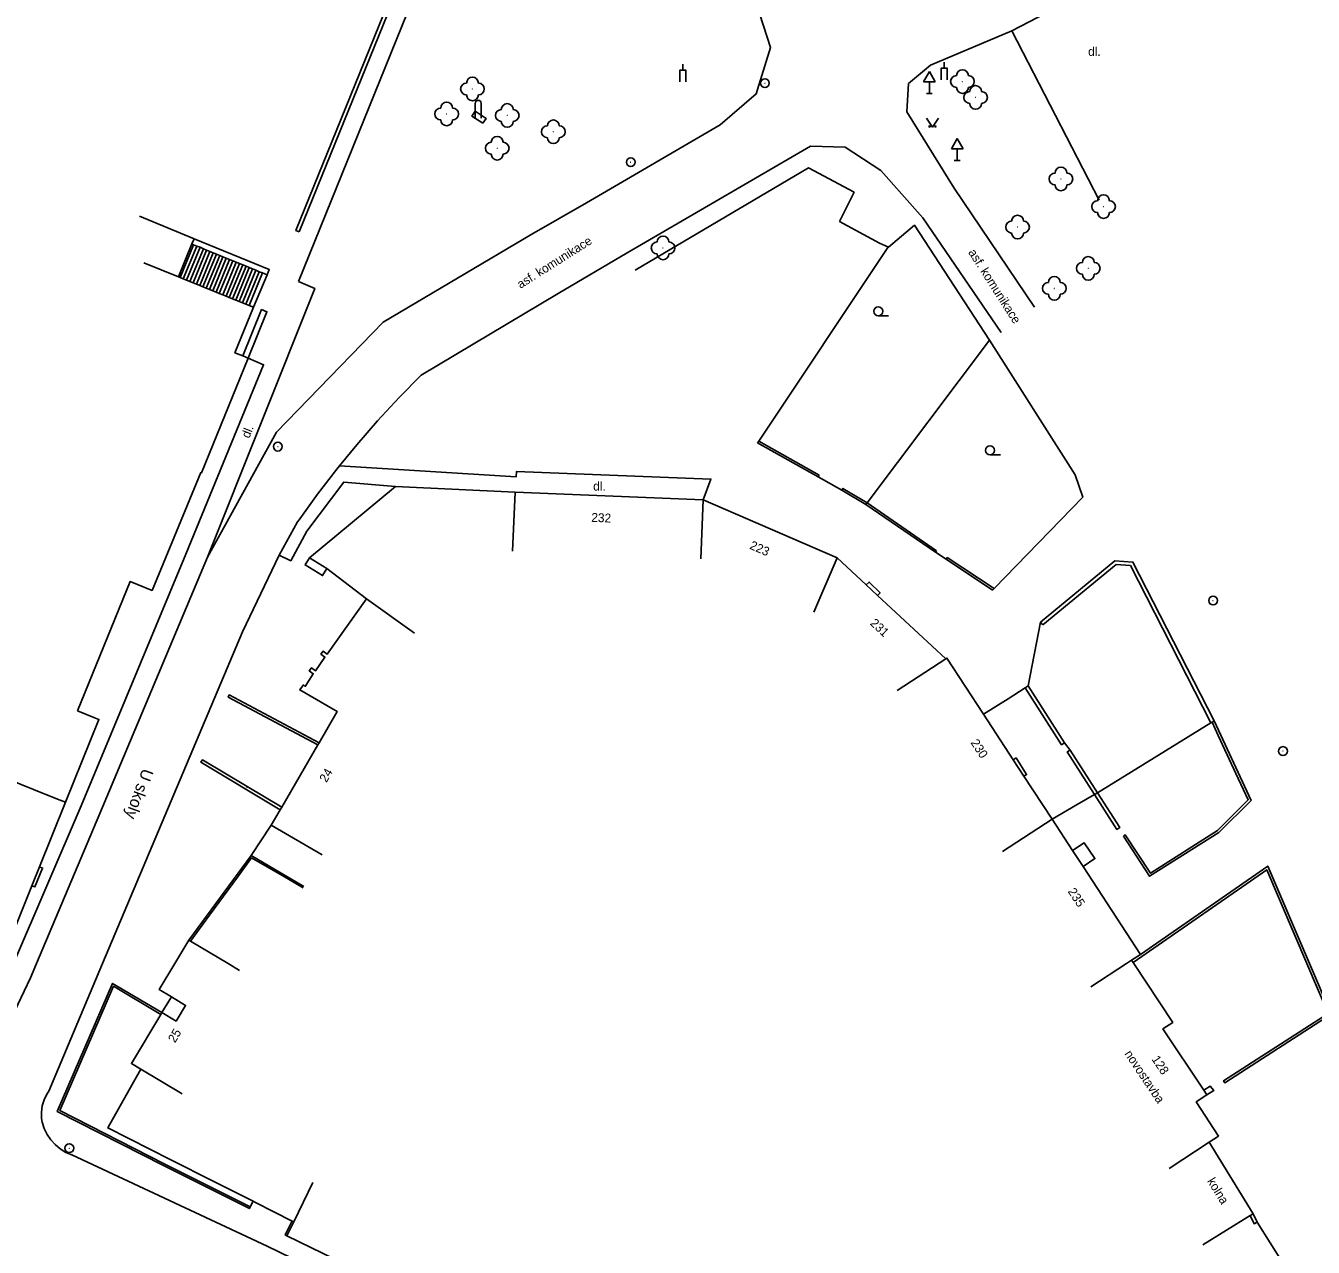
# Model space of a CAD drawing. Extents: x -582162 to -561283, y -1187583 to -1183539.
# Drawn here: x -578373.5 to -578264.6, y -1186024 to -1185920.7 of the extents above; entities that cross this region are included whole.
import ezdxf

# ---------------------------------------------------------------- set-up
doc = ezdxf.new("R2010")
doc.units = 0
for name, color, linetype in [('Vrstva 1', 7, 'Continuous'), ('Vrstva 10', 7, 'Continuous'), ('Vrstva 11', 7, 'Continuous'), ('Vrstva 13', 7, 'Continuous'), ('Vrstva 14', 7, 'Continuous'), ('Vrstva 3', 7, 'Continuous'), ('Vrstva 4', 7, 'Continuous'), ('Vrstva 6', 7, 'Continuous'), ('Vrstva 9', 7, 'Continuous')]:
    doc.layers.add(name, color=color, linetype=linetype)

# ---------------------------------------------------------------- blocks, each defined once
blk = doc.blocks.new('1.079')
at = {"layer": 'Vrstva 1'}
for radius in [0.75, 0.001]:
    blk.add_circle((0, -0.001), radius, dxfattribs=at)
blk = doc.blocks.new('3.130')
at = {"layer": 'Vrstva 1'}
blk.add_circle((0, 0), 0.001, dxfattribs=at)
for centre, start, end in [((-1, 0), 90, 270), ((0, 1), 0, 180), ((1, 0), 270, 90), ((0, -1), 180, 360)]:
    blk.add_arc(centre, 1, start, end, dxfattribs=at)
blk = doc.blocks.new('3.040')
at = {"layer": 'Vrstva 1'}
blk.add_line((0, -0.75), (1.75, -0.75), dxfattribs=at)
blk.add_circle((0, 0), 0.75, dxfattribs=at)
blk = doc.blocks.new('3.140')
at = {"layer": 'Vrstva 1'}
blk.add_lwpolyline([(-1, 1.5), (0, 0), (1, 1.5)], dxfattribs=at)
for centre in [(-0.5, 0.1), (0.5, 0.1)]:
    blk.add_circle(centre, 0.1, dxfattribs=at)
blk = doc.blocks.new('4.120')
at = {"layer": 'Vrstva 1'}
blk.add_line((0, 2), (0, 3), dxfattribs=at)
blk.add_lwpolyline([(-0.5, 0), (-0.5, 2), (0.5, 2), (0.5, 0)], dxfattribs=at)
blk = doc.blocks.new('4.140')
at = {"layer": 'Vrstva 1'}
for p, q in [((-0.5, 0), (-0.5, 2.5)), ((0.5, 0), (0.5, 2.5))]:
    blk.add_line(p, q, dxfattribs=at)
blk.add_arc((0, 2.5), 0.5, 0, 180, dxfattribs=at)
blk = doc.blocks.new('5.270')
at = {"layer": 'Vrstva 1'}
for p, q in [((0, 3.732), (-1, 2)), ((0, 3.732), (1, 2)), ((-1, 2), (1, 2)), ((-0.5, 0), (0.5, 0)), ((0, 0), (0, 2))]:
    blk.add_line(p, q, dxfattribs=at)

msp = doc.modelspace()

# ---------------------------------------------------------------- linework, layer by layer
at = {"layer": 'Vrstva 10'}
for points in [[(-578326.04, -1185935.66), (-578314.74, -1185929.06), (-578311.68, -1185926.46), (-578310.47, -1185922.53), (-578312.01, -1185917.81), (-578316.2, -1185914.48), (-578322.8, -1185910.47), (-578334.12, -1185904.09)], [(-578335.19, -1185904.77), (-578350.39, -1185942.33)], [(-578290.07, -1185921.12), (-578284.27, -1185918.07)], [(-578290.07, -1185921.12), (-578296.93, -1185924.04), (-578298.81, -1185925.58), (-578298.94, -1185927.96), (-578294.95, -1185934.42), (-578288.14, -1185944.49)], [(-578290.07, -1185921.12), (-578282.68, -1185935.44)], [(-578334.8, -1185928.94), (-578335.72, -1185928.33), (-578335.44, -1185927.92), (-578334.53, -1185928.53), (-578334.8, -1185928.94)], [(-578290.96, -1185946.64), (-578297.58, -1185936.93), (-578301.15, -1185932.93), (-578304.17, -1185930.95), (-578307.1, -1185930.89), (-578322.61, -1185939.9)], [(-578343.24, -1185945.76), (-578330.66, -1185938.33), (-578326.04, -1185935.66)], [(-578353.05, -1185941.76), (-578352.86, -1185941.32), (-578359.23, -1185938.7)], [(-578360.41, -1185941.98), (-578359.27, -1185939.21)], [(-578360.14, -1185942.09), (-578358.99, -1185939.32)], [(-578359.86, -1185942.2), (-578358.72, -1185939.43)], [(-578359.58, -1185942.31), (-578358.44, -1185939.55)], [(-578359.27, -1185939.21), (-578359.41, -1185939.15)], [(-578359.3, -1185942.43), (-578358.16, -1185939.66)], [(-578358.99, -1185939.32), (-578359.27, -1185939.21)], [(-578359.02, -1185942.54), (-578357.88, -1185939.78)], [(-578358.72, -1185939.43), (-578358.99, -1185939.32)], [(-578358.75, -1185942.65), (-578357.61, -1185939.89)], [(-578358.44, -1185939.55), (-578358.72, -1185939.43)], [(-578358.47, -1185942.77), (-578357.33, -1185940)], [(-578358.16, -1185939.66), (-578358.44, -1185939.55)], [(-578358.2, -1185942.88), (-578357.05, -1185940.12)], [(-578357.88, -1185939.78), (-578358.16, -1185939.66)], [(-578357.61, -1185939.89), (-578357.88, -1185939.78)], [(-578357.33, -1185940), (-578357.61, -1185939.89)], [(-578357.05, -1185940.12), (-578357.33, -1185940)], [(-578356.78, -1185940.23), (-578357.05, -1185940.12)], [(-578322.61, -1185939.9), (-578328.44, -1185943.34), (-578340.01, -1185950.23)], [(-578357.91, -1185943), (-578356.78, -1185940.23)], [(-578357.63, -1185943.11), (-578356.5, -1185940.34)], [(-578357.35, -1185943.22), (-578356.22, -1185940.46)], [(-578357.09, -1185943.33), (-578355.94, -1185940.58)], [(-578356.8, -1185943.45), (-578355.67, -1185940.69)], [(-578356.5, -1185940.34), (-578356.78, -1185940.23)], [(-578356.52, -1185943.56), (-578355.39, -1185940.8)], [(-578356.22, -1185940.46), (-578356.5, -1185940.34)], [(-578356.25, -1185943.67), (-578355.11, -1185940.92)], [(-578355.94, -1185940.58), (-578356.22, -1185940.46)], [(-578355.98, -1185943.78), (-578354.83, -1185941.03)], [(-578355.67, -1185940.69), (-578355.94, -1185940.58)], [(-578355.69, -1185943.9), (-578354.56, -1185941.14)], [(-578355.39, -1185940.8), (-578355.67, -1185940.69)], [(-578355.41, -1185944.01), (-578354.28, -1185941.26)], [(-578355.11, -1185940.92), (-578355.39, -1185940.8)], [(-578354.83, -1185941.03), (-578355.11, -1185940.92)], [(-578354.56, -1185941.14), (-578354.83, -1185941.03)], [(-578354.28, -1185941.26), (-578354.56, -1185941.14)], [(-578354, -1185941.37), (-578354.28, -1185941.26)], [(-578350.39, -1185942.33), (-578349.02, -1185942.9), (-578358.08, -1185965.64)], [(-578355.13, -1185944.12), (-578354, -1185941.37)], [(-578354.85, -1185944.23), (-578353.72, -1185941.49)], [(-578354.57, -1185944.34), (-578353.45, -1185941.6)], [(-578354.21, -1185944.49), (-578353.05, -1185941.76)], [(-578353.72, -1185941.49), (-578354, -1185941.37)], [(-578353.45, -1185941.6), (-578353.72, -1185941.49)], [(-578353.05, -1185941.76), (-578353.45, -1185941.6)], [(-578354.66, -1185948.79), (-578353.06, -1185944.88), (-578353.51, -1185944.7), (-578355.1, -1185948.61)], [(-578358.08, -1185965.64), (-578352.25, -1185955.07), (-578343.24, -1185945.76)], [(-578374.5, -1186000), (-578368.76, -1185986.67), (-578359.91, -1185965.38), (-578353.34, -1185949.36), (-578354.66, -1185948.79)], [(-578340.01, -1185950.23), (-578341.88, -1185952.14), (-578343.7, -1185954.1), (-578345.45, -1185956.12), (-578346.92, -1185957.91)], [(-578346.92, -1185957.91), (-578347.15, -1185958.19), (-578348.78, -1185960.31), (-578350.35, -1185962.48), (-578350.47, -1185962.65), (-578352.02, -1185965.46)], [(-578316.17, -1185960.77), (-578315.52, -1185959.03), (-578331.96, -1185958.39), (-578331.99, -1185958.84), (-578346.92, -1185957.91)], [(-578342.2, -1185959.66), (-578346.57, -1185959.28), (-578349.69, -1185963.42), (-578351.05, -1185965.94), (-578352.02, -1185965.46)], [(-578304.43, -1185959.96), (-578306.43, -1185958.83)], [(-578295.62, -1185965.81), (-578296.53, -1185965.22)], [(-578358.08, -1185965.64), (-578367.19, -1185987.3), (-578372.56, -1186000)], [(-578352.02, -1185965.46), (-578355.12, -1185971.94), (-578366.96, -1186000)], [(-578347.99, -1185966.59), (-578348.35, -1185967.19), (-578349.84, -1185966.29), (-578349.47, -1185965.69)], [(-578349.47, -1185965.69), (-578347.99, -1185966.59)], [(-578301.42, -1185968.86), (-578301.21, -1185968.64), (-578302.12, -1185967.74), (-578302.37, -1185967.98)], [(-578285.13, -1185981.94), (-578285.61, -1185981.32)], [(-578289.95, -1185982.76), (-578289.71, -1185982.61), (-578288.82, -1185984.01), (-578289.04, -1185984.15)], [(-578354.73, -1185985.03), (-578354.78, -1185985.1)], [(-578354.4, -1185990.87), (-578352.7, -1185988.3)], [(-578284.92, -1185990.45), (-578283.94, -1185989.79), (-578283.04, -1185991.12), (-578284.04, -1185991.79)], [(-578372.94, -1185993.42), (-578372.68, -1185993.52), (-578372.04, -1185991.92), (-578372.3, -1185991.82)], [(-578372.56, -1186000), (-578373.06, -1186001.19), (-578375.19, -1186005.72), (-578377.88, -1186010), (-578378.19, -1186010.37), (-578378.55, -1186010.68), (-578378.95, -1186010.91), (-578379.39, -1186011.08), (-578379.85, -1186011.16), (-578380.31, -1186011.17), (-578380.78, -1186011.1), (-578381.22, -1186010.95), (-578381.63, -1186010.73), (-578405.48, -1186000)], [(-578366.96, -1186000), (-578371.51, -1186010.78), (-578371.68, -1186011.05), (-578371.9, -1186011.53), (-578372.06, -1186012.04), (-578372.13, -1186012.57), (-578372.12, -1186013.1), (-578372.06, -1186013.41), (-578371.89, -1186013.94), (-578371.65, -1186014.44), (-578371.34, -1186014.9), (-578370.97, -1186015.31), (-578370.54, -1186015.67), (-578370.06, -1186015.96), (-578369.55, -1186016.18), (-578353.03, -1186023.9), (-578334.84, -1186032.75), (-578321.02, -1186039.95), (-578303.35, -1186050.31), (-578281.8, -1186064.68)], [(-578361.94, -1186004.14), (-578360.74, -1186004.86), (-578359.94, -1186003.53), (-578361.14, -1186002.81)], [(-578273.56, -1186011.09), (-578272.98, -1186010.73), (-578273.28, -1186010.37), (-578273.82, -1186010.7)], [(-578354.24, -1186020.1), (-578354.47, -1186020.57)], [(-578350.94, -1186021.77), (-578351.51, -1186022.94), (-578351.37, -1186023.01)], [(-578269.31, -1186021.87), (-578267.13, -1186025.35)]]:
    msp.add_lwpolyline(points, dxfattribs=at)
at = {"layer": 'Vrstva 4'}
for points in [[(-578359.23, -1185938.7), (-578363.85, -1185936.8)], [(-578359.41, -1185939.15), (-578359.23, -1185938.7)], [(-578360.55, -1185941.92), (-578359.41, -1185939.15)], [(-578360.55, -1185941.92), (-578363.47, -1185940.73)], [(-578360.41, -1185941.98), (-578360.55, -1185941.92)], [(-578360.14, -1185942.09), (-578360.41, -1185941.98)], [(-578359.86, -1185942.2), (-578360.14, -1185942.09)], [(-578359.58, -1185942.31), (-578359.86, -1185942.2)], [(-578359.3, -1185942.43), (-578359.58, -1185942.31)], [(-578359.02, -1185942.54), (-578359.3, -1185942.43)], [(-578358.75, -1185942.65), (-578359.02, -1185942.54)], [(-578358.47, -1185942.77), (-578358.75, -1185942.65)], [(-578358.2, -1185942.88), (-578358.47, -1185942.77)], [(-578357.91, -1185943), (-578358.2, -1185942.88)], [(-578357.63, -1185943.11), (-578357.91, -1185943)], [(-578357.35, -1185943.22), (-578357.63, -1185943.11)], [(-578357.09, -1185943.33), (-578357.35, -1185943.22)], [(-578356.8, -1185943.45), (-578357.09, -1185943.33)], [(-578356.52, -1185943.56), (-578356.8, -1185943.45)], [(-578356.25, -1185943.67), (-578356.52, -1185943.56)], [(-578355.98, -1185943.78), (-578356.25, -1185943.67)], [(-578355.69, -1185943.9), (-578355.98, -1185943.78)], [(-578355.1, -1185948.61), (-578355.77, -1185948.34), (-578354.21, -1185944.49)], [(-578355.41, -1185944.01), (-578355.69, -1185943.9)], [(-578355.13, -1185944.12), (-578355.41, -1185944.01)], [(-578354.85, -1185944.23), (-578355.13, -1185944.12)], [(-578354.57, -1185944.34), (-578354.85, -1185944.23)], [(-578354.21, -1185944.49), (-578354.57, -1185944.34)], [(-578369.07, -1185978.62), (-578364.64, -1185967.69), (-578362.77, -1185968.45), (-578358.66, -1185958.48), (-578358.59, -1185958.5), (-578354.66, -1185948.79)], [(-578354.66, -1185948.79), (-578355.1, -1185948.61)], [(-578332.07, -1185960.13), (-578332.28, -1185965.12)], [(-578316.17, -1185960.77), (-578332.07, -1185960.13)], [(-578316.37, -1185965.77), (-578316.17, -1185960.77)], [(-578304.83, -1185965.7), (-578316.17, -1185960.77)], [(-578306.82, -1185970.28), (-578304.83, -1185965.7)], [(-578302.37, -1185967.98), (-578304.83, -1185965.7)], [(-578301.42, -1185968.86), (-578302.37, -1185967.98)], [(-578348.65, -1185981.34), (-578347.11, -1185978.69), (-578350.29, -1185976.85), (-578349.98, -1185976.44), (-578349.82, -1185976.56), (-578349.14, -1185975.49), (-578349.48, -1185975.24), (-578349.3, -1185975), (-578348.96, -1185975.25), (-578348.16, -1185974.08), (-578348.5, -1185973.83), (-578348.32, -1185973.59), (-578347.98, -1185973.84), (-578344.63, -1185969.16)], [(-578344.63, -1185969.16), (-578340.57, -1185972.07)], [(-578295.64, -1185974.22), (-578301.42, -1185968.86)], [(-578299.75, -1185976.9), (-578295.64, -1185974.22)], [(-578295.64, -1185974.22), (-578295.56, -1185974.17), (-578292.46, -1185978.92)], [(-578370.11, -1185986.36), (-578367.27, -1185979.35), (-578367.7, -1185979.18)], [(-578367.7, -1185979.18), (-578369.07, -1185978.62)], [(-578292.46, -1185978.92), (-578289.95, -1185982.76)], [(-578351.81, -1185986.77), (-578348.75, -1185981.51)], [(-578348.75, -1185981.51), (-578348.65, -1185981.34)], [(-578289.95, -1185982.76), (-578289.04, -1185984.15)], [(-578374.75, -1185984.5), (-578371.91, -1185985.64)], [(-578289.04, -1185984.15), (-578286.66, -1185987.79)], [(-578371.91, -1185985.64), (-578370.55, -1185986.18)], [(-578370.11, -1185986.36), (-578372.3, -1185991.82)], [(-578370.55, -1185986.18), (-578370.11, -1185986.36)], [(-578352.7, -1185988.3), (-578351.94, -1185986.99)], [(-578351.94, -1185986.99), (-578351.81, -1185986.77)], [(-578290.85, -1185990.52), (-578286.66, -1185987.79)], [(-578286.66, -1185987.79), (-578284.92, -1185990.45)], [(-578348.38, -1185990.81), (-578352.7, -1185988.3)], [(-578284.92, -1185990.45), (-578284.04, -1185991.79)], [(-578372.3, -1185991.82), (-578372.94, -1185993.42)], [(-578284.04, -1185991.79), (-578279.19, -1185999.23)], [(-578372.94, -1185993.42), (-578375.58, -1186000)], [(-578359.66, -1185998.01), (-578360.85, -1186000)], [(-578359.53, -1185998.09), (-578359.66, -1185998.01)], [(-578356.34, -1186000), (-578359.53, -1185998.09)], [(-578360.85, -1186000), (-578362.17, -1186002.2), (-578361.14, -1186002.81)], [(-578355.37, -1186000.58), (-578356.34, -1186000)], [(-578280.37, -1186000), (-578283.37, -1186001.96)], [(-578279.93, -1185999.71), (-578280.37, -1186000)], [(-578279.19, -1185999.23), (-578279.93, -1185999.71)], [(-578279.93, -1185999.71), (-578279.81, -1185999.9)], [(-578279.81, -1185999.9), (-578279.74, -1186000)], [(-578279.74, -1186000), (-578276.46, -1186004.97), (-578277.29, -1186005.52), (-578273.82, -1186010.7)], [(-578361.14, -1186002.81), (-578361.94, -1186004.14)], [(-578362.03, -1186004.29), (-578364.52, -1186008.45), (-578363.72, -1186008.93)], [(-578361.94, -1186004.14), (-578362.03, -1186004.29)], [(-578363.72, -1186008.93), (-578360.24, -1186011.02)], [(-578273.82, -1186010.7), (-578273.56, -1186011.09)], [(-578273.56, -1186011.09), (-578274.47, -1186011.7), (-578272.59, -1186014.58), (-578273.37, -1186015.09)], [(-578273.37, -1186015.09), (-578276.76, -1186017.32)], [(-578273.37, -1186015.09), (-578269.65, -1186021.15)], [(-578349.18, -1186018.51), (-578350.8, -1186021.84)], [(-578350.8, -1186021.84), (-578351.37, -1186023.01)], [(-578269.91, -1186021.31), (-578273.91, -1186023.77)], [(-578269.65, -1186021.15), (-578269.91, -1186021.31)], [(-578351.37, -1186023.01), (-578334.11, -1186031.42)]]:
    msp.add_lwpolyline(points, dxfattribs=at)
at = {"layer": 'Vrstva 9'}
for points in [[(-578347.57, -1185930.52), (-578338.04, -1185907), (-578358.01, -1185896.59)], [(-578350.33, -1185938.13), (-578347.3, -1185930.63), (-578337.66, -1185906.86)], [(-578347.57, -1185930.52), (-578350.61, -1185938.02), (-578350.33, -1185938.13)], [(-578304.64, -1185937.26), (-578303.4, -1185934.77), (-578307.26, -1185932.72), (-578321.93, -1185941.36)], [(-578301.26, -1185939.08), (-578304.64, -1185937.26)], [(-578291.95, -1185947.29), (-578298.3, -1185937.57), (-578300.5, -1185939.42), (-578301.26, -1185939.08)], [(-578300.55, -1185939.46), (-578311.47, -1185955.83)], [(-578291.95, -1185947.29), (-578302.31, -1185961.04)], [(-578291.55, -1185968.29), (-578284.07, -1185960.56), (-578284.7, -1185958.66), (-578291.95, -1185947.29)], [(-578311.47, -1185955.83), (-578311.56, -1185955.96)], [(-578306.43, -1185958.83), (-578311.56, -1185955.96)], [(-578311.47, -1185955.83), (-578306.36, -1185958.69)], [(-578306.43, -1185958.83), (-578306.36, -1185958.69)], [(-578342.2, -1185959.66), (-578349.47, -1185965.69)], [(-578332.07, -1185960.13), (-578342.2, -1185959.66)], [(-578302.31, -1185961.04), (-578304.35, -1185959.82), (-578304.43, -1185959.96)], [(-578302.41, -1185961.17), (-578304.43, -1185959.96)], [(-578302.31, -1185961.04), (-578302.41, -1185961.17)], [(-578296.53, -1185965.22), (-578302.41, -1185961.17)], [(-578302.31, -1185961.04), (-578296.44, -1185965.09)], [(-578296.53, -1185965.22), (-578296.44, -1185965.09)], [(-578295.62, -1185965.81), (-578295.53, -1185965.67)], [(-578291.69, -1185968.43), (-578295.62, -1185965.81)], [(-578295.53, -1185965.67), (-578291.55, -1185968.29)], [(-578287.64, -1185971.12), (-578281.34, -1185965.94), (-578279.83, -1185966.05), (-578272.96, -1185979.48)], [(-578281.25, -1185966.25), (-578287.45, -1185971.35)], [(-578281.25, -1185966.25), (-578280.02, -1185966.34)], [(-578273.22, -1185979.64), (-578280.02, -1185966.34)], [(-578347.99, -1185966.59), (-578344.63, -1185969.16)], [(-578291.69, -1185968.43), (-578291.55, -1185968.29)], [(-578287.64, -1185971.12), (-578288.69, -1185976.52)], [(-578287.45, -1185971.35), (-578287.64, -1185971.12)], [(-578288.94, -1185976.68), (-578290.38, -1185977.6)], [(-578288.69, -1185976.52), (-578288.94, -1185976.68)], [(-578285.61, -1185981.32), (-578285.86, -1185981.49), (-578288.94, -1185976.68)], [(-578285.61, -1185981.32), (-578288.69, -1185976.52)], [(-578348.75, -1185981.51), (-578356.34, -1185977.46), (-578356.25, -1185977.28), (-578348.65, -1185981.34)], [(-578290.38, -1185977.6), (-578292.46, -1185978.92)], [(-578273.22, -1185979.64), (-578282.82, -1185985.56)], [(-578272.96, -1185979.48), (-578269.83, -1185986.2), (-578272.56, -1185988.91), (-578278.41, -1185992.62), (-578280.62, -1185989.22)], [(-578273.13, -1185979.58), (-578273.22, -1185979.64)], [(-578272.96, -1185979.48), (-578273.13, -1185979.58)], [(-578272.6, -1185980.72), (-578273.13, -1185979.58)], [(-578270.91, -1185984.34), (-578272.6, -1185980.72)], [(-578285.13, -1185981.94), (-578285.38, -1185982.1), (-578283.08, -1185985.71)], [(-578282.82, -1185985.56), (-578285.13, -1185981.94)], [(-578351.94, -1185986.99), (-578358.65, -1185982.98), (-578358.52, -1185982.77), (-578354.73, -1185985.03)], [(-578271.26, -1185987.34), (-578270.07, -1185986.15), (-578270.91, -1185984.34)], [(-578354.73, -1185985.03), (-578351.81, -1185986.77)], [(-578283.08, -1185985.71), (-578284.55, -1185986.56)], [(-578283.08, -1185985.71), (-578281.17, -1185988.65), (-578280.92, -1185988.49), (-578282.82, -1185985.56)], [(-578282.82, -1185985.56), (-578283.08, -1185985.71)], [(-578284.55, -1185986.56), (-578286.66, -1185987.79)], [(-578272.68, -1185988.75), (-578271.26, -1185987.34)], [(-578280.62, -1185989.22), (-578280.47, -1185989.12), (-578278.35, -1185992.35), (-578272.68, -1185988.75)], [(-578359.66, -1185998.01), (-578354.4, -1185990.87)], [(-578351.73, -1185992.59), (-578354.36, -1185991.07), (-578355.54, -1185992.68)], [(-578349.93, -1185993.47), (-578354.4, -1185990.87)], [(-578265.12, -1186000), (-578268.5, -1185992.07), (-578279.81, -1185999.9)], [(-578279.19, -1185999.23), (-578268.42, -1185991.76), (-578264.9, -1186000)], [(-578355.54, -1185992.68), (-578357.92, -1185995.9)], [(-578350, -1185993.6), (-578351.73, -1185992.59)], [(-578357.92, -1185995.9), (-578359.53, -1185998.09)], [(-578264.9, -1186000), (-578263.07, -1186004.28), (-578272.05, -1186010.08), (-578272.16, -1186009.91), (-578263.32, -1186004.21), (-578265.12, -1186000)], [(-578354.47, -1186020.57), (-578354.55, -1186020.72), (-578361.82, -1186017.07), (-578370.81, -1186012.5), (-578366.11, -1186001.67), (-578361.94, -1186004.14)], [(-578362.03, -1186004.29), (-578366.03, -1186001.92), (-578370.59, -1186012.42), (-578361.75, -1186016.92), (-578354.47, -1186020.57)], [(-578363.72, -1186008.93), (-578364.71, -1186010.68)], [(-578364.71, -1186010.68), (-578366.53, -1186013.9), (-578364.75, -1186014.8)], [(-578364.75, -1186014.8), (-578361.18, -1186016.6)], [(-578361.18, -1186016.6), (-578357.6, -1186018.41)], [(-578357.6, -1186018.41), (-578354.24, -1186020.1)], [(-578354.24, -1186020.1), (-578354.03, -1186020.21)], [(-578354.03, -1186020.21), (-578350.94, -1186021.77)], [(-578350.94, -1186021.77), (-578350.8, -1186021.84)], [(-578269.91, -1186021.31), (-578269.58, -1186022), (-578269.31, -1186021.87)], [(-578269.65, -1186021.15), (-578269.31, -1186021.87)]]:
    msp.add_lwpolyline(points, dxfattribs=at)

# ---------------------------------------------------------------- block references
at = {"layer": 'Vrstva 1', "xscale": 0.5, "yscale": 0.5}
for p in [(-578310.95, -1185925.55), (-578322.29, -1185932.23), (-578352.14, -1185956.28), (-578273.04, -1185969.3), (-578267.13, -1185982.03), (-578369.78, -1186015.61)]:
    msp.add_blockref('1.079', p, dxfattribs=at)
at = {"layer": 'Vrstva 11', "xscale": 0.5, "yscale": 0.5}
for p in [(-578294.24, -1185925.41), (-578335.68, -1185926.04), (-578293.13, -1185926.76), (-578337.86, -1185928.15), (-578332.74, -1185928.28), (-578328.84, -1185929.66), (-578333.59, -1185931.05), (-578285.91, -1185933.65), (-578282.31, -1185935.99), (-578289.58, -1185937.72), (-578319.56, -1185939.48), (-578283.6, -1185941.21), (-578286.47, -1185942.9)]:
    msp.add_blockref('3.130', p, dxfattribs=at)
at = {"layer": 'Vrstva 3', "xscale": 0.5, "yscale": 0.5}
for name, p in [('3.140', (-578296.77, -1185929.26)), ('3.040', (-578301.36, -1185944.84)), ('3.040', (-578291.91, -1185956.6))]:
    msp.add_blockref(name, p, dxfattribs=at)
at = {"layer": 'Vrstva 9', "xscale": 0.5, "yscale": 0.5}
for name, p in [('4.120', (-578295.79, -1185925.28)), ('4.120', (-578317.89, -1185925.44)), ('5.270', (-578297.04, -1185926.43)), ('4.140', (-578335.19, -1185928.51)), ('5.270', (-578294.68, -1185932.09))]:
    msp.add_blockref(name, p, dxfattribs=at)

# ---------------------------------------------------------------- texts
at = {"layer": 'Vrstva 13'}
msp.add_text('U skoly', height=1, rotation=249.955, dxfattribs=at).set_placement((-578363.57, -1185983.44))
at = {"layer": 'Vrstva 14'}
for p in [(-578283.61, -1185923.24), (-578325.47, -1185960)]:
    msp.add_text('dl.', height=0.75, dxfattribs=at).set_placement(p)
for s, rotation, p in [('asf. komunikace', 32.333, (-578331.62, -1185942.95)), ('asf. komunikace', 302.552, (-578293.78, -1185939.86)), ('dl.', 68.276, (-578354.56, -1185955.63)), ('novostavba', 303.839, (-578280.57, -1186007.63)), ('kolna', 301.543, (-578273.57, -1186018.39))]:
    msp.add_text(s, height=0.75, rotation=rotation, dxfattribs=at).set_placement(p)
at = {"layer": 'Vrstva 6'}
for s, rotation, p in [('232', 357.674, (-578325.64, -1185962.64)), ('223', 336.522, (-578312.3, -1185964.9)), ('231', 317.143, (-578302.11, -1185971.29)), ('230', 303.173, (-578293.58, -1185981.32)), ('24', 59.808, (-578348.03, -1185984.74)), ('235', 303.163, (-578285.36, -1185993.9)), ('25', 59.081, (-578360.84, -1186006.76)), ('128', 303.839, (-578278.28, -1186008.08))]:
    msp.add_text(s, height=0.75, rotation=rotation, dxfattribs=at).set_placement(p)

doc.saveas('drawing.dxf')
